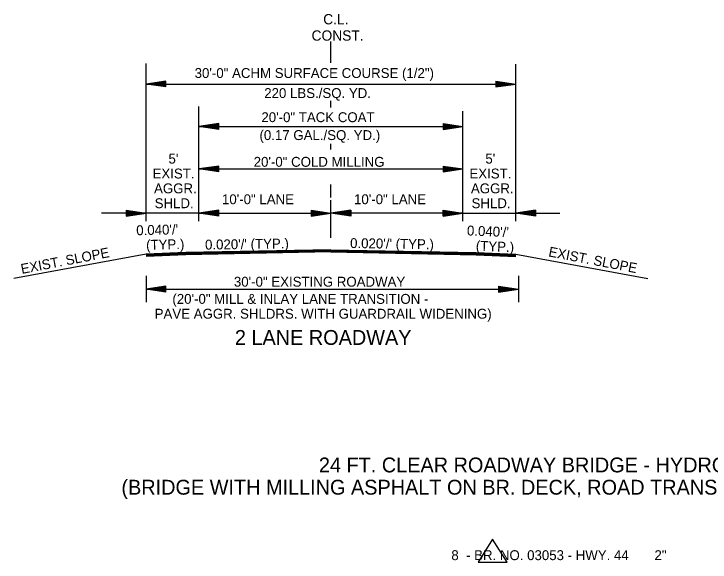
# Model space of a CAD drawing. Extents: x 544259 to 1930787, y -1961343 to 596640.
# Drawn here: x 544376 to 544903, y -1961295 to -1960880 of the extents above; entities that cross this region are included whole.
import ezdxf

# ---------------------------------------------------------------- set-up
doc = ezdxf.new("R2010")
doc.units = 0
doc.layers.add('R_Border', color=7, linetype='Continuous')
doc.layers.add('R_Draft', color=7, linetype='Continuous')

msp = doc.modelspace()

# ---------------------------------------------------------------- linework, layer by layer
at = {"layer": 'R_Border'}
for p, q in [((544506.07, -1961060.81), (544476.07, -1961062.01)), ((544506.07, -1961061.11), (544476.07, -1961062.31)), ((544506.07, -1961061.41), (544476.07, -1961062.61)), ((544506.07, -1961061.71), (544476.07, -1961062.91)), ((544506.07, -1961062.01), (544476.07, -1961063.21)), ((544506.07, -1961062.31), (544476.07, -1961063.51)), ((544506.07, -1961062.48), (544476.07, -1961063.68)), ((544726.07, -1961060.81), (544756.07, -1961062.01)), ((544726.07, -1961061.11), (544756.07, -1961062.31)), ((544726.07, -1961061.41), (544756.07, -1961062.61)), ((544726.07, -1961061.71), (544756.07, -1961062.91)), ((544726.07, -1961062.01), (544756.07, -1961063.21)), ((544726.07, -1961062.31), (544756.07, -1961063.51)), ((544726.07, -1961062.48), (544756.07, -1961063.68)), ((544738.56, -1961278.03), (544727.52, -1961295.33)), ((544749.6, -1961295.33), (544738.56, -1961278.03)), ((544727.52, -1961295.33), (544749.6, -1961295.33))]:
    msp.add_line(p, q, dxfattribs=at)
at = {"layer": 'R_Draft'}
for p, q in [((544616.07, -1960917.04), (544616.07, -1960900.96)), ((544476.07, -1961036.88), (544476.07, -1960917.54)), ((544756.07, -1961036.88), (544756.07, -1960918.1)), ((544491.07, -1960930.83), (544476.07, -1960933.08)), ((544491.07, -1960931.21), (544478.57, -1960933.08)), ((544491.07, -1960931.59), (544481.15, -1960933.08)), ((544491.07, -1960931.97), (544483.65, -1960933.08)), ((544491.07, -1960932.35), (544486.19, -1960933.08)), ((544491.07, -1960932.73), (544488.7, -1960933.08)), ((544491.07, -1960935.33), (544491.07, -1960930.83)), ((544741.07, -1960930.83), (544756.07, -1960933.08)), ((544741.07, -1960930.83), (544741.07, -1960935.33)), ((544741.07, -1960931.21), (544753.56, -1960933.08)), ((544741.07, -1960931.59), (544750.98, -1960933.08)), ((544741.07, -1960931.97), (544748.48, -1960933.08)), ((544741.07, -1960932.36), (544745.94, -1960933.08)), ((544741.07, -1960932.73), (544743.44, -1960933.08)), ((544476.07, -1960933.08), (544756.07, -1960933.08)), ((544491.07, -1960935.33), (544476.07, -1960933.08)), ((544491.07, -1960934.96), (544478.57, -1960933.08)), ((544491.07, -1960934.58), (544481.15, -1960933.08)), ((544491.07, -1960934.2), (544483.65, -1960933.08)), ((544491.07, -1960933.81), (544486.19, -1960933.08)), ((544491.07, -1960933.44), (544488.7, -1960933.08)), ((544741.07, -1960935.33), (544756.07, -1960933.08)), ((544741.07, -1960933.82), (544745.94, -1960933.08)), ((544741.07, -1960934.58), (544750.98, -1960933.08)), ((544741.07, -1960934.96), (544753.56, -1960933.08)), ((544741.07, -1960934.2), (544748.48, -1960933.08)), ((544741.07, -1960933.44), (544743.44, -1960933.08)), ((544616.07, -1960950.97), (544616.07, -1960945.94)), ((544516.07, -1961036.88), (544516.07, -1960950.06)), ((544716.07, -1961036.88), (544716.07, -1960953.73)), ((544531.07, -1960962.98), (544516.07, -1960965.23)), ((544531.07, -1960963.36), (544518.57, -1960965.23)), ((544531.07, -1960963.74), (544521.15, -1960965.23)), ((544531.07, -1960964.11), (544523.65, -1960965.23)), ((544531.07, -1960964.5), (544526.19, -1960965.23)), ((544531.07, -1960967.48), (544531.07, -1960962.98)), ((544701.07, -1960962.98), (544716.07, -1960965.23)), ((544701.07, -1960962.98), (544701.07, -1960967.48)), ((544701.07, -1960963.36), (544713.56, -1960965.23)), ((544701.07, -1960963.74), (544710.98, -1960965.23)), ((544701.07, -1960964.11), (544708.48, -1960965.23)), ((544701.07, -1960964.5), (544705.94, -1960965.23)), ((544516.07, -1960965.23), (544716.07, -1960965.23)), ((544531.07, -1960967.48), (544516.07, -1960965.23)), ((544531.07, -1960967.11), (544518.57, -1960965.23)), ((544531.07, -1960966.72), (544521.15, -1960965.23)), ((544531.07, -1960966.35), (544523.65, -1960965.23)), ((544531.07, -1960965.96), (544526.19, -1960965.23)), ((544531.07, -1960964.88), (544528.7, -1960965.23)), ((544531.07, -1960965.58), (544528.7, -1960965.23)), ((544701.07, -1960964.88), (544703.44, -1960965.23)), ((544701.07, -1960967.48), (544716.07, -1960965.23)), ((544701.07, -1960965.97), (544705.94, -1960965.23)), ((544701.07, -1960966.72), (544710.98, -1960965.23)), ((544701.07, -1960967.11), (544713.56, -1960965.23)), ((544701.07, -1960966.35), (544708.48, -1960965.23)), ((544701.07, -1960965.58), (544703.44, -1960965.23)), ((544616.07, -1960982.82), (544616.07, -1960978.36)), ((544531.07, -1960995.22), (544516.07, -1960997.47)), ((544531.07, -1960995.6), (544518.57, -1960997.47)), ((544531.07, -1960995.98), (544521.15, -1960997.47)), ((544531.07, -1960999.72), (544531.07, -1960995.22)), ((544701.07, -1960995.22), (544716.07, -1960997.47)), ((544701.07, -1960995.22), (544701.07, -1960999.72)), ((544701.07, -1960995.6), (544713.56, -1960997.47)), ((544701.07, -1960995.98), (544710.98, -1960997.47)), ((544516.07, -1960997.47), (544716.07, -1960997.47)), ((544531.07, -1960999.72), (544516.07, -1960997.47)), ((544531.07, -1960999.35), (544518.57, -1960997.47)), ((544531.07, -1960998.96), (544521.15, -1960997.47)), ((544531.07, -1960996.35), (544523.65, -1960997.47)), ((544531.07, -1960998.59), (544523.65, -1960997.47)), ((544531.07, -1960996.74), (544526.19, -1960997.47)), ((544531.07, -1960998.2), (544526.19, -1960997.47)), ((544531.07, -1960997.12), (544528.7, -1960997.47)), ((544531.07, -1960997.82), (544528.7, -1960997.47)), ((544701.07, -1960996.35), (544708.48, -1960997.47)), ((544701.07, -1960996.74), (544705.94, -1960997.47)), ((544701.07, -1960997.12), (544703.44, -1960997.47)), ((544701.07, -1960999.72), (544716.07, -1960997.47)), ((544701.07, -1960998.21), (544705.94, -1960997.47)), ((544701.07, -1960998.96), (544710.98, -1960997.47)), ((544701.07, -1960999.35), (544713.56, -1960997.47)), ((544701.07, -1960998.59), (544708.48, -1960997.47)), ((544701.07, -1960997.82), (544703.44, -1960997.47)), ((544616.07, -1961011.01), (544616.07, -1961009.12)), ((544616.07, -1961018.99), (544616.07, -1961011.01)), ((544616.07, -1961049.67), (544616.07, -1961021.12)), ((544516.07, -1961031.01), (544442.34, -1961031.01)), ((544461.07, -1961028.76), (544476.07, -1961031.01)), ((544461.07, -1961028.76), (544461.07, -1961033.26)), ((544461.07, -1961029.13), (544473.56, -1961031.01)), ((544461.07, -1961029.52), (544470.98, -1961031.01)), ((544461.07, -1961029.89), (544468.48, -1961031.01)), ((544461.07, -1961030.28), (544465.94, -1961031.01)), ((544461.07, -1961030.66), (544463.44, -1961031.01)), ((544461.07, -1961033.26), (544476.07, -1961031.01)), ((544461.07, -1961031.74), (544465.94, -1961031.01)), ((544461.07, -1961032.5), (544470.98, -1961031.01)), ((544461.07, -1961032.88), (544473.56, -1961031.01)), ((544461.07, -1961032.13), (544468.48, -1961031.01)), ((544461.07, -1961031.36), (544463.44, -1961031.01)), ((544531.07, -1961028.76), (544516.07, -1961031.01)), ((544531.07, -1961033.26), (544516.07, -1961031.01)), ((544516.07, -1961031.01), (544616.07, -1961031.01)), ((544531.07, -1961029.13), (544518.57, -1961031.01)), ((544531.07, -1961032.88), (544518.57, -1961031.01)), ((544531.07, -1961029.52), (544521.15, -1961031.01)), ((544531.07, -1961032.5), (544521.15, -1961031.01)), ((544531.07, -1961029.89), (544523.65, -1961031.01)), ((544531.07, -1961032.13), (544523.65, -1961031.01)), ((544531.07, -1961030.27), (544526.19, -1961031.01)), ((544531.07, -1961031.74), (544526.19, -1961031.01)), ((544531.07, -1961030.66), (544528.7, -1961031.01)), ((544531.07, -1961031.36), (544528.7, -1961031.01)), ((544531.07, -1961033.26), (544531.07, -1961028.76)), ((544601.07, -1961028.76), (544616.07, -1961031.01)), ((544601.07, -1961028.76), (544601.07, -1961033.26)), ((544601.07, -1961029.13), (544613.56, -1961031.01)), ((544601.07, -1961029.52), (544610.98, -1961031.01)), ((544601.07, -1961029.89), (544608.48, -1961031.01)), ((544601.07, -1961030.28), (544605.94, -1961031.01)), ((544601.07, -1961030.66), (544603.44, -1961031.01)), ((544601.07, -1961033.26), (544616.07, -1961031.01)), ((544601.07, -1961031.74), (544605.94, -1961031.01)), ((544601.07, -1961032.5), (544610.98, -1961031.01)), ((544601.07, -1961032.88), (544613.56, -1961031.01)), ((544601.07, -1961032.13), (544608.48, -1961031.01)), ((544601.07, -1961031.36), (544603.44, -1961031.01)), ((544631.07, -1961028.76), (544616.07, -1961031.01)), ((544716.07, -1961031.01), (544616.07, -1961031.01)), ((544631.07, -1961033.26), (544616.07, -1961031.01)), ((544631.07, -1961029.13), (544618.57, -1961031.01)), ((544631.07, -1961032.88), (544618.57, -1961031.01)), ((544631.07, -1961029.52), (544621.15, -1961031.01)), ((544631.07, -1961032.5), (544621.15, -1961031.01)), ((544631.07, -1961029.89), (544623.65, -1961031.01)), ((544631.07, -1961032.13), (544623.65, -1961031.01)), ((544631.07, -1961030.28), (544626.19, -1961031.01)), ((544631.07, -1961031.74), (544626.19, -1961031.01)), ((544631.07, -1961030.66), (544628.7, -1961031.01)), ((544631.07, -1961031.36), (544628.7, -1961031.01)), ((544631.07, -1961028.76), (544631.07, -1961033.26)), ((544701.07, -1961028.76), (544716.07, -1961031.01)), ((544701.07, -1961033.26), (544701.07, -1961028.76)), ((544701.07, -1961029.13), (544713.56, -1961031.01)), ((544701.07, -1961029.52), (544710.98, -1961031.01)), ((544701.07, -1961029.89), (544708.48, -1961031.01)), ((544701.07, -1961030.27), (544705.94, -1961031.01)), ((544701.07, -1961030.66), (544703.44, -1961031.01)), ((544701.07, -1961033.26), (544716.07, -1961031.01)), ((544701.07, -1961031.74), (544705.94, -1961031.01)), ((544701.07, -1961032.5), (544710.98, -1961031.01)), ((544701.07, -1961032.88), (544713.56, -1961031.01)), ((544701.07, -1961032.13), (544708.48, -1961031.01)), ((544701.07, -1961031.36), (544703.44, -1961031.01)), ((544716.18, -1961031.01), (544789.53, -1961031.01)), ((544771.07, -1961028.76), (544756.07, -1961031.01)), ((544771.07, -1961033.26), (544756.07, -1961031.01)), ((544771.07, -1961029.13), (544758.57, -1961031.01)), ((544771.07, -1961032.88), (544758.57, -1961031.01)), ((544771.07, -1961029.52), (544761.15, -1961031.01)), ((544771.07, -1961032.5), (544761.15, -1961031.01)), ((544771.07, -1961029.89), (544763.65, -1961031.01)), ((544771.07, -1961032.13), (544763.65, -1961031.01)), ((544771.07, -1961030.28), (544766.19, -1961031.01)), ((544771.07, -1961031.74), (544766.19, -1961031.01)), ((544771.07, -1961030.66), (544768.7, -1961031.01)), ((544771.07, -1961031.36), (544768.7, -1961031.01)), ((544771.07, -1961028.76), (544771.07, -1961033.26)), ((544616.07, -1961058.61), (544506.07, -1961060.81)), ((544616.06, -1961058.91), (544506.07, -1961061.11)), ((544616.07, -1961059.21), (544506.07, -1961061.41)), ((544616.08, -1961059.51), (544506.07, -1961061.71)), ((544616.05, -1961059.21), (544726.07, -1961061.41)), ((544616.05, -1961059.51), (544726.07, -1961061.71)), ((544616.06, -1961058.91), (544726.07, -1961061.11)), ((544616.07, -1961058.61), (544726.07, -1961060.81)), ((544476.07, -1961062.01), (544376, -1961080.39)), ((544616.09, -1961059.81), (544506.07, -1961062.01)), ((544616.1, -1961060.11), (544506.07, -1961062.31)), ((544616.1, -1961060.28), (544506.07, -1961062.48)), ((544616.03, -1961060.28), (544726.07, -1961062.48)), ((544616.04, -1961059.81), (544726.07, -1961062.01)), ((544616.04, -1961060.11), (544726.07, -1961062.31)), ((544756.07, -1961062.01), (544856.13, -1961080.39)), ((544476.07, -1961078.47), (544476.07, -1961098.47)), ((544758.07, -1961078.47), (544758.07, -1961098.47)), ((544491.07, -1961086.22), (544476.07, -1961088.47)), ((544476.07, -1961088.47), (544756.07, -1961088.47)), ((544491.07, -1961090.72), (544476.07, -1961088.47)), ((544491.07, -1961086.6), (544478.57, -1961088.47)), ((544491.07, -1961090.35), (544478.57, -1961088.47)), ((544491.07, -1961086.98), (544481.15, -1961088.47)), ((544491.07, -1961089.97), (544481.15, -1961088.47)), ((544491.07, -1961087.36), (544483.65, -1961088.47)), ((544491.07, -1961089.59), (544483.65, -1961088.47)), ((544491.07, -1961087.74), (544486.19, -1961088.47)), ((544491.07, -1961089.2), (544486.19, -1961088.47)), ((544491.07, -1961088.12), (544488.7, -1961088.47)), ((544491.07, -1961088.83), (544488.7, -1961088.47)), ((544491.07, -1961090.72), (544491.07, -1961086.22)), ((544743.07, -1961086.22), (544758.07, -1961088.47)), ((544743.07, -1961086.22), (544743.07, -1961090.72)), ((544743.07, -1961086.6), (544755.56, -1961088.47)), ((544743.07, -1961086.98), (544752.98, -1961088.47)), ((544743.07, -1961087.36), (544750.48, -1961088.47)), ((544743.07, -1961087.75), (544747.94, -1961088.47)), ((544743.07, -1961088.12), (544745.44, -1961088.47)), ((544743.07, -1961090.72), (544758.07, -1961088.47)), ((544743.07, -1961089.21), (544747.94, -1961088.47)), ((544743.07, -1961089.97), (544752.98, -1961088.47)), ((544743.07, -1961090.35), (544755.56, -1961088.47)), ((544743.07, -1961089.59), (544750.48, -1961088.47)), ((544743.07, -1961088.83), (544745.44, -1961088.47))]:
    msp.add_line(p, q, dxfattribs=at)

# ---------------------------------------------------------------- texts
for s, height, p in [('C.L.', 7.8, (544610.22, -1960887.87)), ('CONST.', 7.8, (544601.44, -1960900.24)), ('30\'-0" ACHM SURFACE COURSE (1/2")', 7.5, (544512.87, -1960928.51)), ('220 LBS./SQ. YD. ', 7.5, (544565.57, -1960943.69)), ('20\'-0" TACK COAT', 7.5, (544563.42, -1960961.98)), ('(0.17 GAL./SQ. YD.)', 7.5, (544561.98, -1960975.53)), ("5' ", 7.5, (544493.05, -1960993.4)), ('20\'-0" COLD MILLING', 7.5, (544557.57, -1960995.8)), ("5' ", 7.5, (544733.04, -1960993.4)), ('EXIST.', 7.5, (544481, -1961004.65)), ('EXIST.', 7.5, (544720.99, -1961004.65)), ('AGGR.', 7.5, (544482.12, -1961015.9)), ('AGGR.', 7.5, (544722.11, -1961015.9)), ('10\'-0" LANE', 7.5, (544533.58, -1961024.15)), ('10\'-0" LANE', 7.5, (544633.58, -1961024.15)), ('SHLD.', 7.5, (544482.6, -1961027.15)), ('SHLD.', 7.5, (544722.59, -1961027.15)), ('30\'-0" EXISTING ROADWAY', 7.5, (544542.6, -1961086.64)), ('(20\'-0" MILL & INLAY LANE TRANSITION -', 7.5, (544496.01, -1961099.65)), ('PAVE AGGR. SHLDRS. WITH GUARDRAIL WIDENING)', 7.5, (544482.6, -1961110.9)), ('2 LANE ROADWAY', 11.25, (544543.34, -1961130.75)), ('24 FT. CLEAR ROADWAY BRIDGE - HYDRODEMOLITION', 11.25, (544606.98, -1961227.36)), ('(BRIDGE WITH MILLING ASPHALT ON BR. DECK, ROAD TRANSITIONS, AND NEW GUARDRAIL)', 11.25, (544457.41, -1961244.23)), ('      8  - BR. NO. 03053 - HWY. 44       2"', 7.5, (544690.56, -1961293.85))]:
    msp.add_text(s, height=height, dxfattribs=at).set_placement(p)
for s, rotation, p in [("0.040'/' ", 1.3184, (544468.72, -1961047.68)), ("0.040'/' ", 357.6456, (544718.97, -1961047.76)), ('(TYP.)', 1.3184, (544476.18, -1961058.76)), ("0.020'/' (TYP.)", 0.8719, (544520.79, -1961058.57)), ("0.020'/' (TYP.)", 359.1281, (544630.56, -1961057.34)), ('(TYP.)', 357.6456, (544725.71, -1961059.29)), ('EXIST. SLOPE', 10.8829, (544381.98, -1961077.01)), ('EXIST. SLOPE', 349.1171, (544780.45, -1961063.61))]:
    msp.add_text(s, height=7.5, rotation=rotation, dxfattribs=at).set_placement(p)

doc.saveas('drawing.dxf')
